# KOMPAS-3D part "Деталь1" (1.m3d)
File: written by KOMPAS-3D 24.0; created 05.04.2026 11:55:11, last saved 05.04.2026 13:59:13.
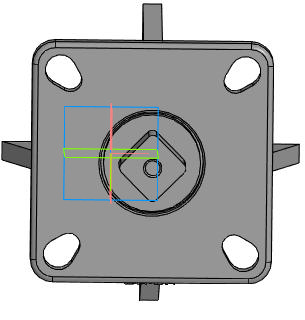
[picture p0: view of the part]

Document properties: Автор: R2D2; Полное имя файла: E:\Работа\Зайцев\Аксессуары для пневмоприводов\Ручной дублер DN.ru\MON4-1200-T54-ISO Ручной дублер DN.ru\исходные материалы\1.m3d

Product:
- Body: Тело 2  | qty 1
    Масса: 4.315995
- Part/product: Деталь1
    Масса: 35.407781
    additional columns: Типовые

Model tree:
1. Операция без истории:1
2. Эскиз:1  (with: Грань.Операция без истории:1, Ребро.Операция без истории:1)
3. Элемент выдавливания:1  (with: Грань.Операция без истории:1)
     Расстояние 1 = -20.8
4. Скругление:1  (with: Ребро.Элемент выдавливания:1)
     Радиус = 3
5. Эскиз:2  (with: Ребро.Операция без истории:1)
6. Элемент выдавливания:2
     Расстояние 1 = 500
7. Эскиз:3  (with: Грань.Операция без истории:1, Ребро.Операция без истории:1)
8. Элемент выдавливания:3
     Расстояние 1 = 50
9. Эскиз:4  (with: Ребро.Операция без истории:1)
10. Элемент выдавливания:4
     Расстояние 1 = 10
11. Массив по концентрической сетке:1  (with: Элемент выдавливания:4, Эскиз:4, Грань.Элемент выдавливания:3)  (4 pattern instances)
     Шаг 2 = 360
12. Эскиз:5  (with: Грань.Операция без истории:1, Ребро.Операция без истории:1)
13. Элемент выдавливания:5
     Расстояние 2 = 20
14. Массив по концентрической сетке:2  (with: Элемент выдавливания:5, Эскиз:5, Грань.Операция без истории:1)  (4 pattern instances)
     Шаг 2 = 360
